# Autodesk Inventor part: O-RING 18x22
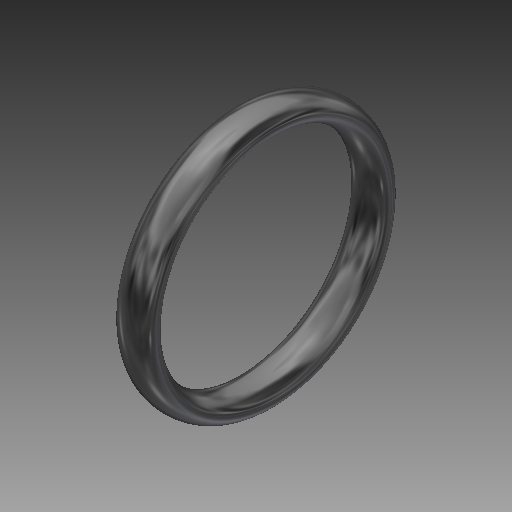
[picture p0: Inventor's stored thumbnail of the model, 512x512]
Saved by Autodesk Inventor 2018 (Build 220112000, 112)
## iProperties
Created: 2020-02
Part Number: O-RING 18x22
Material: 고무
Document SubType Name: Modeling
Designer: mduedu
Density: 1 g/cm^3
Appearance: 고무 - 검은색 - 버전 1.1
Author: mduedu
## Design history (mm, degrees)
sketch "스케치1"
  geometry: L1 (-2.24, 0)-(2.24, 0) reference; L2 (-1.6, 10)-(1.6, 10); L3 (0, 11)-(0, 9); 6 further points; 1 other entity
  constraints: 4 coincident, 4 end point, 2 horizontal, 2 midpoint, 1 vertical, 1 vertical alignment, 6 other
  dimensions: "d0" = 18 diameter of point (0, 9) L1; "d1" = 22 diameter of point (0, 11) L1; "d2" = 1.6 distance from line of point (1.6, 10) L3
revolve "회전1" sketch "스케치1" stored, may be unused: angle "d3" = 90 deg
node "솔리드1"
